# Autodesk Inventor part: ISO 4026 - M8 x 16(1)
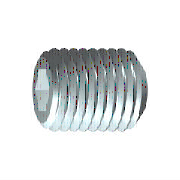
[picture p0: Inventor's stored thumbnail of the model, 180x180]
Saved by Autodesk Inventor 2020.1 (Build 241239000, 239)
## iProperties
Created: 2019-01
Part Number: ISO 4026 - M8 x 16(1)
Material: Edelstahl, 440C
Description: Innensechskant-Gewindestifte mit Kegelstumpf
Document SubType Name: Modeling
Standard: ISO 4026
Designer: lutzd
Standard Revision: Third edition 2003-12-01
Standards Organization: ISO
Language: de-DE
Size Designation: M8 x 16
Categories: <MemberInstance><Categories><Category DisplayName="Verbindungselemente" InternalName="e4da775c-781d-43d5-af7c-5136215cf5a6" Mnemonic="FSTN"><Category DisplayNam
Mass: 5.53264 g
Surface Area: 5.51598 cm^2
Volume: 0.713889 cm^3
Density: 7.75 g/cm^3
Appearance: Halbpoliert
IsCustomPart: 0
Author: lutzd
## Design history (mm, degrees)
sketch "Skizze1"
  geometry: L1 (0, 0)-(9.667, 0); L2 (16, 2.309)-(16, 4); L3 (16, 4)-(0, 4); L4 (16, 2.309)-(11, 2.309); L5 (11, 2.309)-(9.667, 0); L6 (0, -0.8)-(0, 4.8) reference; L7 (0, 4)-(0, 0)
  constraints: 13 end point, 3 parallel, 1 collinear, 1 perpendicular, 1 point on line
  dimensions: "d0" = 5 distance of L2.start L4.end (= INTI); "d1" = 60 deg angle of L5 L1; "d2" = 8 diameter of L3 L1 (= NND); "d3" = 4.6188 diameter of L4 L1 (= 1.1547 x SW); "d5" = 16 distance from line of L2 L3.end (= NLG)
revolve "Körper" sketch "Skizze1" stored, may be unused: angle "d6" = 90 deg
sketch "Skizze2"
  geometry: L1 (-1.155, 2)-(1.155, 2); L2 (1.155, 2)-(2.309, 0); L3 (2.309, 0)-(1.155, -2); L4 (1.155, -2)-(-1.155, -2); L5 (-1.155, -2)-(-2.309, 0); L6 (-2.309, 0)-(-1.155, 2); A1 r 2.309 centre (0, 0) between (-1.155, 2) and (1.155, 2) reference; 2 further points
  constraints: 12 end point, 2 point on circle, 1 coincident, 1 horizontal, 11 other
extrude "Loch" join sketch "Skizze2" taper "d9" = 0 deg; stored distance "d21" = 10
workaxis "Work Axis1"
workplane "Work Plane1"
body "Solid1"
chamfer "Fase1" distance "d7" = 0.76681 (= -0.5 x GD1 + 0.5 x NND); stored, may be unused: angle "d8" = 45 deg (= FAWI), second distance "d29" = 0.76681 (= -0.5 x GD1 + 0.5 x NND)
feature "Gewinde" dims "d11" = 16 (= NLG), "d12" = 0
chamfer "Fase2" distance "d13" = 0.76681 (= -0.5 x GD1 + 0.5 x NND); stored, may be unused: angle "d14" = 45 deg (= FAWI), second distance "d30" = 0.76681 (= -0.5 x GD1 + 0.5 x NND)
other parameters: "NND" = 8 [user parameter; used in 5 equation terms], "NLG" = 16 [user parameter; used in 2 equation terms], "INTI" = 5 [user parameter; used in 1 equation term], "FAWI" = 45 deg [user parameter; used in 2 equation terms], "SW" = 4 [user parameter; used in 2 equation terms], "GD1" = 6.46637 (= THREADDIA - 1.2269 x PTC) [user parameter; used in 4 equation terms], "d4" = 0, "FAWI1" = 45 deg [user parameter], "d15" = 0, "d31" = 0, "GUL" = 0.76681 (= 0.61345 x PTC) [user parameter], "SPD" = 5.5 [user parameter], "SEWI" = 90 deg [user parameter], "TOA" = 30 deg [user parameter], "THREADDIA" = 8 [user parameter; used in 1 equation term], "TPU" = 8 (computed from PTC) [user parameter], "PTC" = 1.25 [user parameter; used in 4 equation terms], "GAL" = 0.76681 (= 0.61345 x PTC) [user parameter], "E0" = 4.62 (= 1.155 x SW) [user parameter]
